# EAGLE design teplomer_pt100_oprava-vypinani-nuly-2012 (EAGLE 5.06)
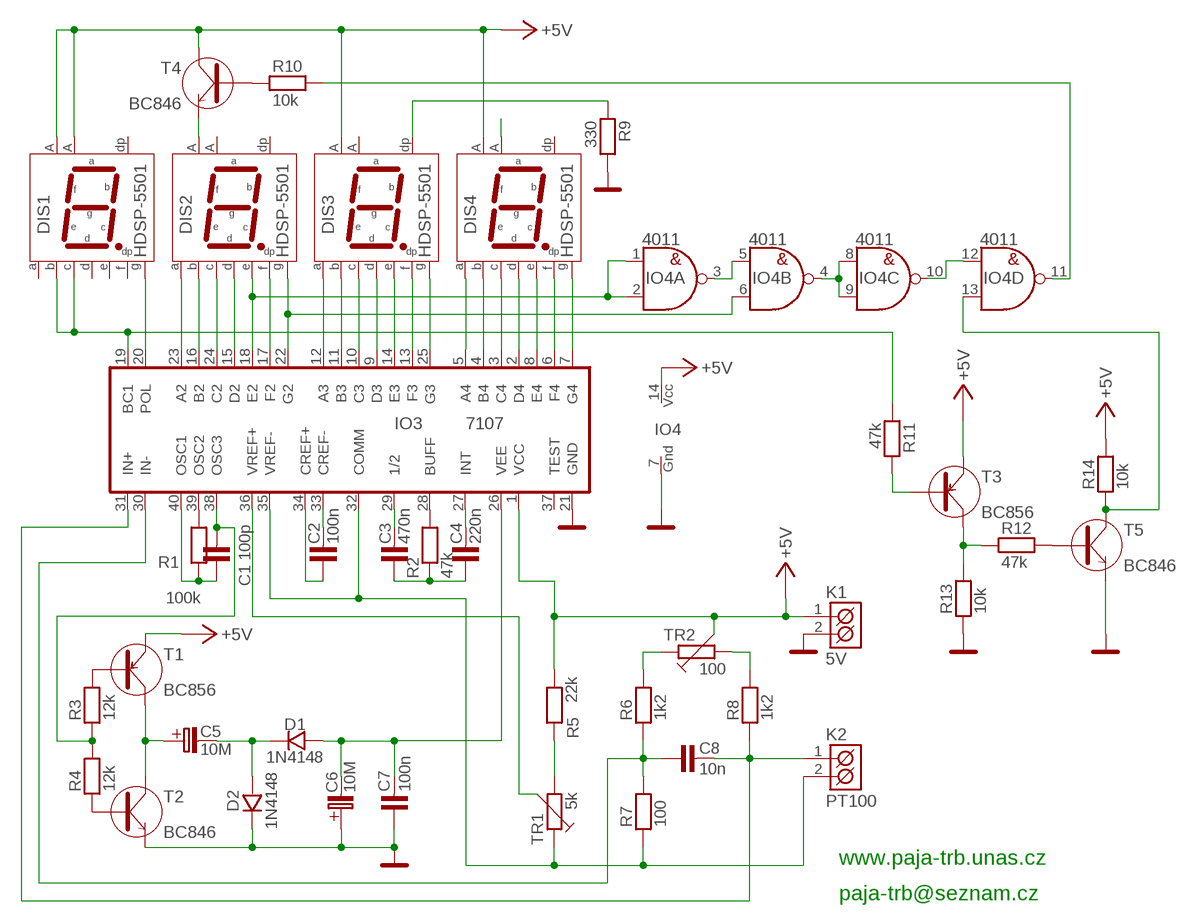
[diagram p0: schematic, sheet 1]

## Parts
C1  100p  C-KERAMIK_SMD_1206  [1206]
C2  100n  100N-J/63V  [RM5_2,5]
C3  470n  470N-J/63V  [RM5_3,2]
C4  220n  220N-J/63V  [RM5_3,2]
C5  10M  10M/25V  [C_EL_2]
C6  10M  10M/25V  [C_EL_2]
C7  100n  C-KERAMIK_SMD_1206  [1206]
C8  10n  C-KERAMIK_SMD_1206  [1206]
D1  1N4148  1N4148_SMD_SOD80  [SOD-80]
D2  1N4148  1N4148_SMD_SOD80  [SOD-80]
DIS1  HDSP-5501  [HDSP-M]
DIS2  HDSP-5501  [HDSP-M]
DIS3  HDSP-5501  [HDSP-M]
DIS4  HDSP-5501  [HDSP-M]
IO3  7107  [DIL40]
IO4  4011  [DIL14]
K1  5V  ARK500/2  [ARK500/2]
K2  PT100  ARK500/2  [ARK500/2]
R1  100k  R_SMD_1206  [1206]
R2  47k  R_SMD_1206  [1206]
R3  12k  R_SMD_1206  [1206]
R4  12k  R_SMD_1206  [1206]
R5  22k  R_SMD_1206  [1206]
R6  1k2  R_SMD_1206  [1206]
R7  100  R_SMD_1206  [1206]
R8  1k2  R_SMD_1206  [1206]
R9  330  R_SMD_1206  [1206]
R10  10k  R_SMD_1206  [1206]
R11  47k  R_SMD_0805  [0805]
R12  47k  R_SMD_0805  [0805]
R13  10k  R_SMD_0805  [0805]
R14  10k  R_SMD_0805  [0805]
T1  BC856  [SOT-23]
T2  BC846  [SOT-23]
T3  BC856  [SOT-23]
T4  BC846  [SOT-23]
T5  BC846  [SOT-23]
TR1  5k  TRIMR64P  [64P]
TR2  100  TRIMR64P  [64P]

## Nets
+5V: DIS1.3(CA1) DIS1.8(CA2) DIS3.3(CA1) DIS4.3(CA1) IO3.1(VCC) IO4.14(N:VCC) K1.1(K1) R5.2 R14.2 T1.1(E) T3.2(E) T4.3(C) TR2.2
GND: C6.C+(C_EL+) C7.1 D2.K IO3.21(GND) IO4.7(N:GND) K1.2(K2) R9.2 R13.1 T2.1(E) T5.2(E)
N$1: IO3.39(OSC2) R1.2
N$2: C2.2 IO3.33(CREF-)
N$3: C1.2 IO3.38(OSC3) R3.1 R4.2
N$4: IO3.28(BUFF) R2.2
N$5: R3.2 T1.2(B)
N$6: R4.1 T2.2(B)
N$7: DIS4.8(CA2)
N$8: C5.C+(C_EL+) T1.3(C) T2.3(C)
N$9: R11.2 T3.1(B)
N$10: DIS2.4(C) IO3.24(C2)
N$11: R12.2 T5.1(B)
N$12: C5.C-(C_EL-) D1.K D2.A
N$13: DIS2.6(B) IO3.16(B2)
N$15: R12.1 R13.2 T3.3(C)
N$16: R5.1 TR1.3
N$17: IO3.32(COMM) IO3.35(VREF-) K2.2(K2) R7.1 TR1.1
N$18: C8.1 IO3.30(IN-) R6.1 R7.2
N$19: R6.2 TR2.1
N$20: R8.2 TR2.3
N$21: C8.2 IO3.31(IN+) K2.1(K1) R8.1
N$22: IO4.13(D:IN2) R14.1 T5.3(C)
N$23: C1.1 IO3.40(OSC1) R1.1
N$24: C2.1 IO3.34(CREF+)
N$25: C3.2 IO3.29(1/2)
N$26: C4.2 IO3.27(INT)
N$27: C3.1 C4.1 R2.1
N$29: IO3.36(VREF+) TR1.2
N$49: DIS2.7(A) IO3.23(A2)
N$50: DIS2.2(D) IO3.15(D2)
N$53: R10.1 T4.2(B)
N$54: DIS2.10(G) IO3.22(G2) IO4.6(B:IN2)
N$55: DIS2.9(F) IO3.17(F2)
N$56: DIS3.4(C) IO3.10(C3)
N$57: DIS3.6(B) IO3.11(B3)
N$58: DIS3.7(A) IO3.12(A3)
N$59: DIS3.2(D) IO3.9(D3)
N$60: DIS3.1(E) IO3.14(E3)
N$61: DIS3.10(G) IO3.25(G3)
N$62: DIS3.9(F) IO3.13(F3)
N$63: DIS4.4(C) IO3.3(C4)
N$64: DIS4.6(B) IO3.4(B4)
N$65: DIS4.7(A) IO3.5(A4)
N$66: DIS4.2(D) IO3.2(D4)
N$67: DIS4.1(E) IO3.8(E4)
N$68: DIS4.10(G) IO3.7(G4)
N$69: DIS4.9(F) IO3.6(F4)
N$71: DIS1.4(C) DIS1.6(B) IO3.19(BC1) R11.1
N$72: DIS1.10(G) IO3.20(POL)
N$73: IO4.11(D:OUT1) R10.2
N$74: DIS2.1(E) IO3.18(E2) IO4.1(A:IN1) IO4.2(A:IN2)
N$75: IO4.3(A:OUT1) IO4.5(B:IN1)
N$76: IO4.4(B:OUT1) IO4.8(C:IN1) IO4.9(C:IN2)
N$77: IO4.10(C:OUT1) IO4.12(D:IN1)
N$78: DIS2.3(CA1) T4.1(E)
N$79: DIS3.5(DP) R9.1
VEE: C6.C-(C_EL-) C7.2 D1.A IO3.26(VEE)
Unconnected: DIS1.1(E) DIS1.2(D) DIS1.5(DP) DIS1.7(A) DIS1.9(F) DIS2.5(DP) DIS2.8(CA2) DIS3.8(CA2) DIS4.5(DP) IO3.37(TEST)

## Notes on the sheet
- 0°C
- 100°C
- www.paja-trb.unas.cz
- paja-trb@seznam.cz

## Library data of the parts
C1 C7 C8 = #PaJa_22:C-KERAMIK: Kondenzator - keramicky
C2 = #PaJa_C-folie:100N-J/63V
C3 = #PaJa_C-folie:470N-J/63V
C4 = #PaJa_C-folie:220N-J/63V
C5 C6 = #PaJa_C-el_2:10M/25V
D1 D2 = #PaJa_22:1N4148: Univerzalni dioda - 0,15A, 75V
DIS1-DIS4 = #PaJa_22:HDSP-5501: LED displej - SA - 14,2 mm - cervena
IO3 = #PaJa_22:7107: IO - A/D prevodnik + budic 7seg. displeje (3 a 1/2 mistny)
IO4 = #PaJa_22:4011: IO - 2vstup. NAND - 4x
K1 K2 = #PaJa_22:ARK500/2: Svorkovnice - roztec 5mm - dvojita
R1-R10 = #PaJa_22:R: Rezistor
R11-R14 = #PaJa_31:R: Rezistor
T1 = #PaJa_22:BC856: SMD tranzistor - PNP - ekv. BC556
T2 T4 = #PaJa_22:BC846: SMD tranzistor - NPN - ekv. BC546
T3 = #PaJa_31:BC856: SMD tranzistor - PNP - ekv. BC556
T5 = #PaJa_31:BC846: SMD tranzistor - NPN - ekv. BC546
TR1 TR2 = #PaJa_22:TRIMR: Trimr

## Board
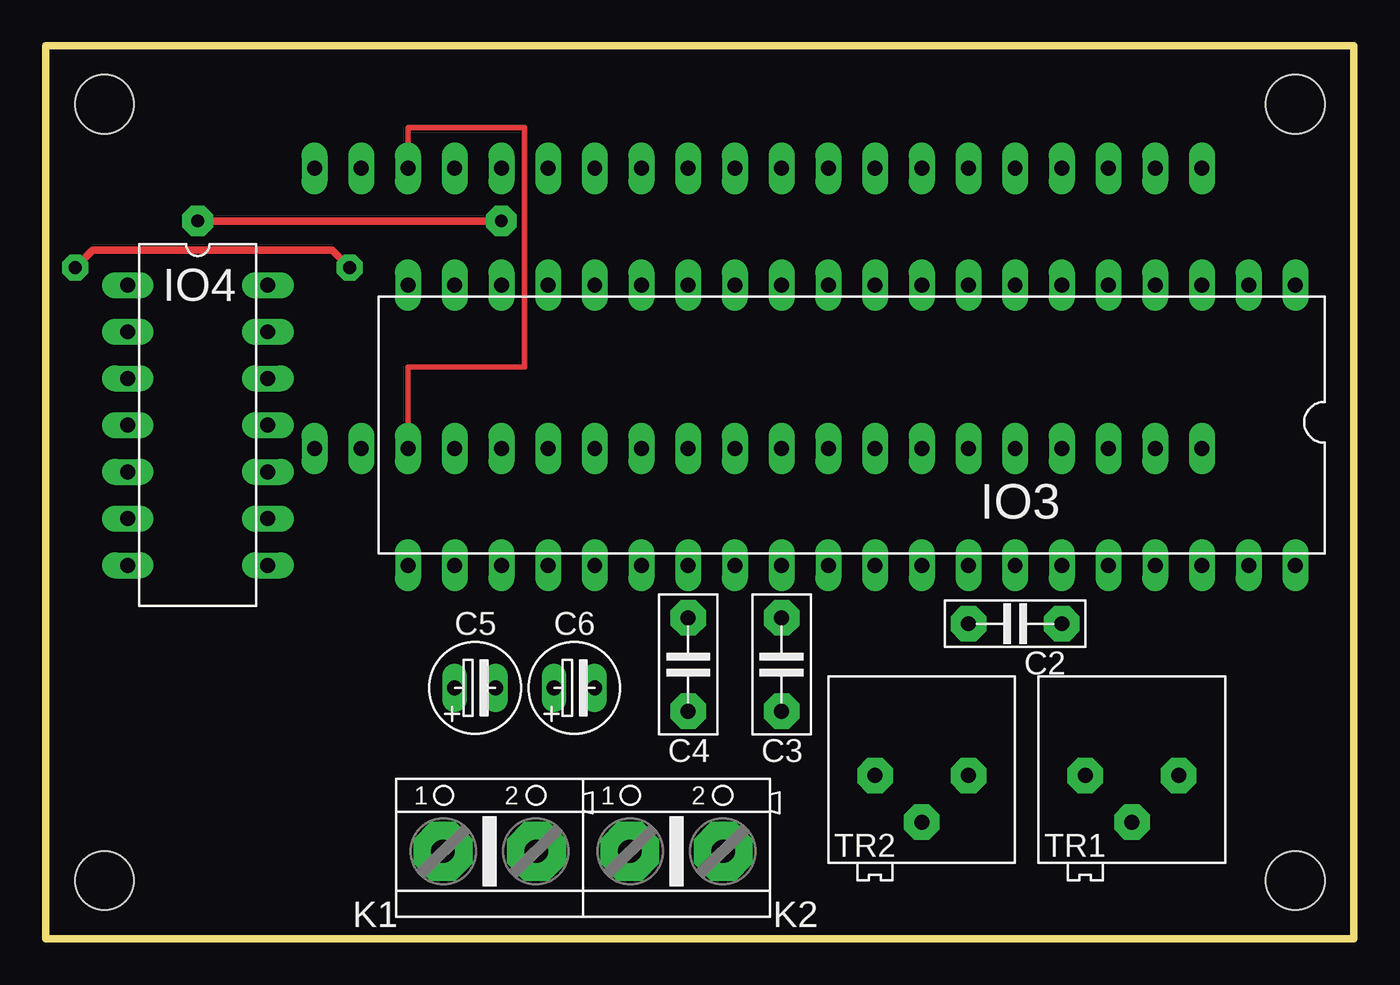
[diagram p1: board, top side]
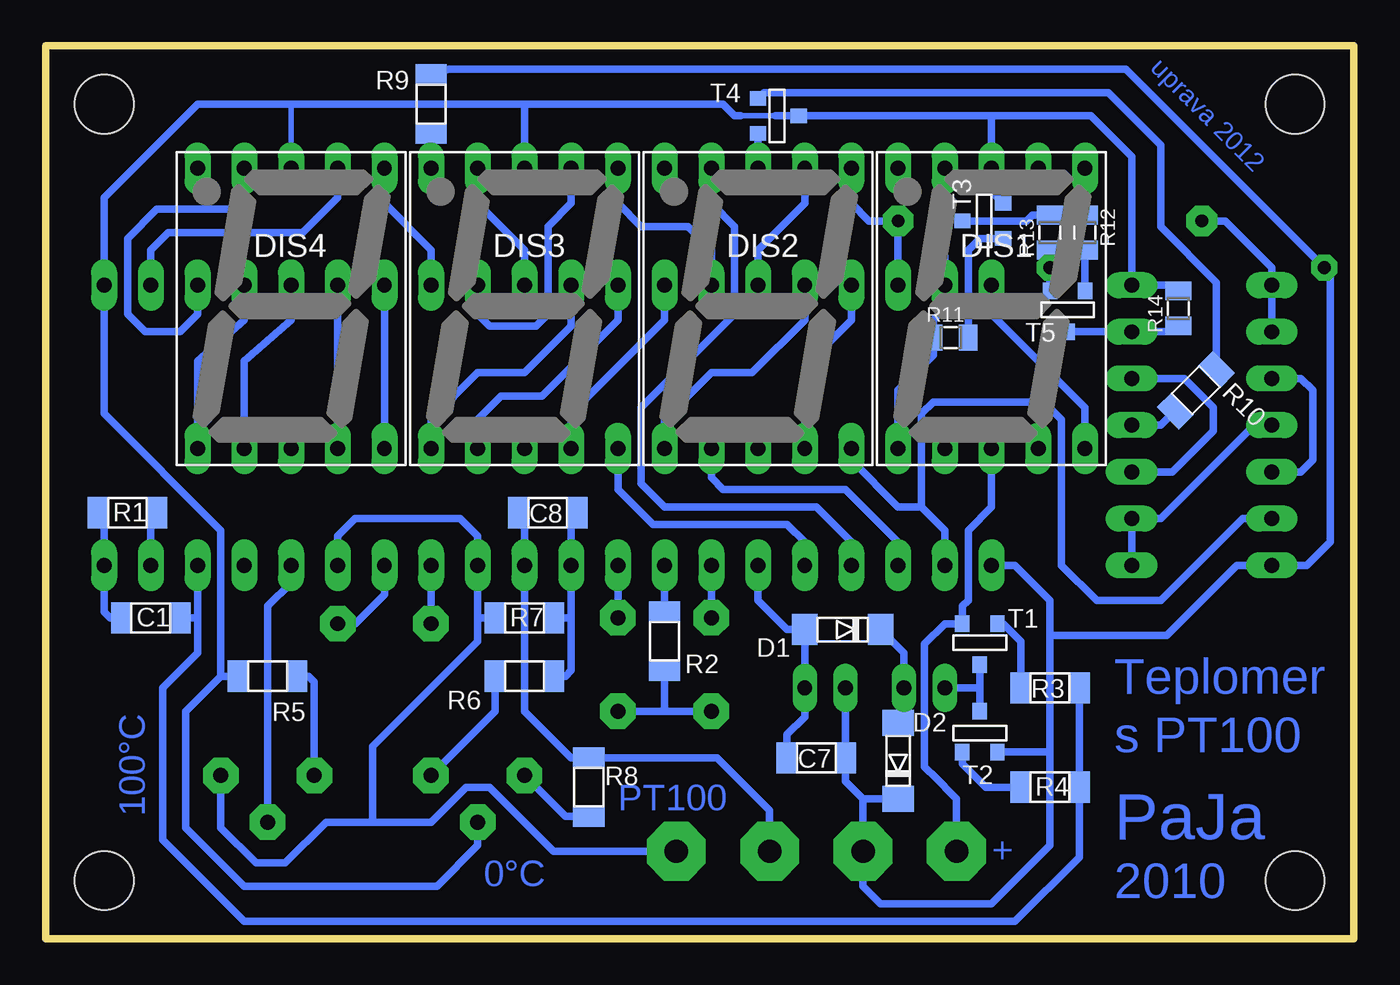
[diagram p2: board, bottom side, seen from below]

Size 71.11 x 48.57 mm. Coordinates in mm from the lower left corner, seen from the top.
Outline: 0,0 71.11,0 71.11,48.57 0,48.57 0,0
Copper layers (1*16): Top 0.035mm / dielectric 1.5mm / Bottom 0.035mm
Design rules "default": minimum track width 10mil, minimum drill 24mil, track to track 8mil, track to pad 8mil, pad to pad 8mil, via to via 8mil, smd to smd 8mil, copper to edge 40mil, drill to drill 8mil, minimum pad ring 10mil, minimum via ring 8mil, stop-mask expansion 4mil, vias tented up to drill 0mil, thermal gap 10mil
Holes 3.2 mm at 3.17,3.17 3.17,45.4 67.94,45.4 67.94,3.17

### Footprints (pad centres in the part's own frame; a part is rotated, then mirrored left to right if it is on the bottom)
1206 = smd 1.143 x 1.702: 1 -1.587,0; 2 1.587,0
RM5_2,5 = drill 0.813 pad 1.93 octagon: 1 -2.54,0; 2 2.54,0
RM5_3,2 = drill 0.813 pad 1.93 octagon: 1 -2.54,0; 2 2.54,0
C_EL_2 = drill 0.813 pad 1.27 long: C+ 0,0; C- 2.223,0
SOD-80 = smd 1.397 x 1.702: A 1.905,0; K -2.223,0
HDSP-M = drill 0.813 pad 1.4 long: 1 -5.08,-7.62; 2 -2.54,-7.62; 3 0,-7.62; 4 2.54,-7.62; 5 5.08,-7.62; 6 5.08,7.62; 7 2.54,7.62; 8 0,7.62; 9 -2.54,7.62; 10 -5.08,7.62
DIL40 = drill 0.813 pad 1.4 long: 1 -22.86,-7.62; 2 -20.32,-7.62; 3 -17.78,-7.62; 4 -15.24,-7.62; 5 -12.7,-7.62; 6 -10.16,-7.62; 7 -7.62,-7.62; 8 -5.08,-7.62; 9 -2.54,-7.62; 10 0,-7.62; 11 2.54,-7.62; 12 5.08,-7.62; 13 7.62,-7.62; 14 10.16,-7.62; 15 12.7,-7.62; 16 15.24,-7.62; 17 17.78,-7.62; 18 20.32,-7.62; 19 22.86,-7.62; 20 25.4,-7.62; 21 25.4,7.62; 22 22.86,7.62; 23 20.32,7.62; 24 17.78,7.62; 25 15.24,7.62; 26 12.7,7.62; 27 10.16,7.62; 28 7.62,7.62; 29 5.08,7.62; 30 2.54,7.62; 31 0,7.62; 32 -2.54,7.62; 33 -5.08,7.62; 34 -7.62,7.62; 35 -10.16,7.62; 36 -12.7,7.62; 37 -15.24,7.62; 38 -17.78,7.62; 39 -20.32,7.62; 40 -22.86,7.62
DIL14 = drill 0.813 pad 1.4 long: 1 -7.62,-3.81; 2 -5.08,-3.81; 3 -2.54,-3.81; 4 0,-3.81; 5 2.54,-3.81; 6 5.08,-3.81; 7 7.62,-3.81; 8 7.62,3.81; 9 5.08,3.81; 10 2.54,3.81; 11 0,3.81; 12 -2.54,3.81; 13 -5.08,3.81; 14 -7.62,3.81
ARK500/2 = drill 1.27 pad 3.2 octagon: 1 -2.54,0; 2 2.54,0
0805 = smd 1.016 x 1.422: 1 -0.953,0; 2 0.953,0
SOT-23 = smd 0.787 x 0.889: 1 0.953,-0.953; 2 -0.953,-0.953; 3 0,1.27
SOT-23' = smd 0.787 x 0.889: 1 -0.953,-0.953; 2 0.953,-0.953; 3 0,1.27
64P = drill 0.813 pad 1.93 octagon: 1 0,2.54; 2 2.54,0; 3 0,-2.54

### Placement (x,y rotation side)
C1  65.41,17.46 0 bottom
C2  52.7,17.14 180 top
C3  40.01,14.92 90 top
C4  34.92,14.92 90 top
C5  22.23,13.65 0 top
C6  27.62,13.65 0 top
C7  29.21,9.84 180 bottom
C8  43.81,23.18 180 bottom
D1  27.94,16.83 180 bottom
D2  24.77,9.84 90 bottom
DIS1  19.68,34.29 180 bottom
DIS2  32.38,34.29 180 bottom
DIS3  45.09,34.29 180 bottom
DIS4  57.78,34.29 180 bottom
IO3  45.09,27.94 180 top
IO4  8.26,27.94 270 top
K1  24.13,4.76 0 top
K2  34.29,4.76 0 top
R1  66.67,23.18 0 bottom
R2  37.47,16.19 90 bottom
R3  16.51,13.65 180 bottom
R4  16.51,8.26 0 bottom
R5  59.05,14.29 180 bottom
R6  45.09,14.29 180 bottom
R7  45.09,17.46 0 bottom
R8  41.59,8.26 270 bottom
R9  50.16,45.4 90 bottom
R10  8.57,29.84 225 bottom
R11  21.91,32.7 0 bottom
R12  14.61,38.42 270 bottom
R13  16.51,38.42 90 bottom
R14  9.53,34.29 90 bottom
T1  20.32,16.19 180 bottom
T2  20.32,11.11 0 bottom
T3  BC856  [SOT-23']  20,39.05 90 bottom
T4  31.43,44.77 270 bottom
T5  BC846  [SOT-23']  15.56,34.29 180 bottom
TR1  59.05,8.89 270 top
TR2  47.62,8.89 270 top

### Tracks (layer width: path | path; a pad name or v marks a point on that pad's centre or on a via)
+5V
  Top 0.305: DIS1.8 19.68,31.11 26.04,31.11 26.04,44.13 19.68,44.13 DIS1.3
  Bottom 0.305: 31.43,44.77 33.34,44.77 | 57.78,45.4 DIS4.3
  Bottom 0.406: 45.09,45.4 57.78,45.4 62.87,45.4 67.94,40.32 IO3.1 67.94,28.57 61.59,22.23 61.59,14.29 | 22.86,8.89 23.18,9.21 23.34,9.37 23.34,16.03 22.23,17.14 T1.1 21.27,18.1 20.95,18.41 20.95,22.23 19.68,23.5 DIS1.8 | 22.86,8.89 | 22.86,8.89 21.59,7.62 K1.1 | DIS1.3 19.68,43.81 | 31.43,44.77 T4.3 19.68,44.77 | 33.34,44.77 33.66,44.77 34.29,45.4 45.09,45.4 | 45.09,45.4 DIS3.3 | TR2.2 47.62,5.08 49.85,2.86 60.33,2.86 63.5,6.03 63.5,12.38 61.59,14.29 | 61.59,14.29 R5.2 | T3.2 19.68,40.64 DIS1.3 | DIS1.3 19.68,44.77 | 19.68,44.77 14.29,44.77 12.06,42.55 IO4.14 9.84,35.56 R14.2
GND  (via drill 0.7 pad 1.42)
  Top 0.406: v16.51,36.51 15.56,37.47 2.54,37.47 v1.59,36.51
  Bottom 0.406: 16.51,10.16 T2.1 | C6.C+ C7.1 27.62,8.57 26.67,7.62 | R9.2 49.21,47.31 12.38,47.31 v1.59,36.51 1.27,36.2 1.27,21.59 2.54,20.32 IO4.7 6.35,20.32 10.16,16.51 16.51,16.51 | IO3.21 18.41,20.32 16.51,18.41 16.51,16.51 | 16.51,10.16 16.51,16.51 | 16.51,10.16 16.51,5.08 19.68,1.91 25.72,1.91 26.67,2.86 K1.2 26.67,7.62 | 26.67,7.62 D2.K | R13.1 v16.51,36.51 T5.2
N$1
  Bottom 0.406: R1.2 65.41,22.86 IO3.39
N$2
  Bottom 0.406: C2.2 IO3.33
N$3
  Bottom 0.406: 62.87,17.46 IO3.38 | R3.1 R4.2 14.92,4.45 18.41,0.95 60.33,0.95 64.77,5.4 64.77,13.65 62.87,15.56 62.87,17.46 | 62.87,17.46 C1.2
N$4
  Bottom 0.406: R2.2 IO3.28
N$5
  Bottom 0.406: R3.2 18.1,16.19 19.05,17.14 T1.2
N$6
  Bottom 0.406: R4.1 20,8.26 21.27,9.53 T2.2
N$8
  Bottom 0.406: 20.32,13.65 C5.C+ | T2.3 20.32,13.65 | 20.32,13.65 T1.3
N$9
  Bottom 0.406: T3.1 20.32,38.1 20.95,37.47 R11.2
N$10
  Bottom 0.406: IO3.24 27.3,21.59 29.21,23.5 37.47,23.5 38.73,24.77 38.73,28.89 33.66,33.97 33.66,38.73 34.92,40.01 DIS2.4
N$11
  Bottom 0.406: T5.1 R12.2
N$12
  Bottom 0.406: D1.K 24.45,15.56 C5.C- 24.45,11.75 D2.A
N$13
  Bottom 0.406: IO3.16 29.84,33.66 32.7,30.8 34.92,30.8 37.47,28.26 DIS2.6
N$15
  Bottom 0.406: R12.1 R13.2 17.46,39.37 17.78,39.05 T3.3
N$16
  Bottom 0.406: R5.1 56.83,14.29 56.52,13.97 TR1.3
N$17
  Bottom 0.406: IO3.35 55.24,21.91 54.29,22.86 48.58,22.86 47.62,21.91 IO3.32 47.62,17.46 | 47.62,17.46 R7.1 | 47.62,17.46 47.62,16.19 53.34,10.48 53.34,6.35 | K2.2 43.5,4.76 46.99,8.26 48.26,8.26 50.16,6.35 53.34,6.35 | TR1.1 61.59,6.03 59.69,4.13 58.1,4.13 55.88,6.35 53.34,6.35
N$18
  Bottom 0.406: 42.55,17.46 R7.2 | 42.55,17.46 IO3.30 42.55,23.18 C8.1 | R6.1 42.86,14.29 42.55,14.61 42.55,17.46
N$19
  Bottom 0.406: R6.2 46.67,12.38 TR2.1
N$20
  Bottom 0.406: R8.2 42.86,6.67 TR2.3
N$21
  Bottom 0.406: C8.2 45.09,23.18 IO3.31 45.09,12.38 42.55,9.84 R8.1 34.61,9.84 31.75,6.99 K2.1
N$22
  Bottom 0.406: R14.1 9.84,33.02 IO4.13 T5.3
N$23
  Bottom 0.406: R1.1 67.94,23.18 IO3.40 67.94,17.78 67.63,17.46 C1.1
N$24
  Bottom 0.406: C2.1 54.29,17.14 52.7,18.73 IO3.34
N$25
  Bottom 0.406: C3.2 IO3.29
N$26
  Bottom 0.406: C4.2 IO3.27
N$27
  Bottom 0.406: 37.47,12.38 R2.1 | C4.1 37.47,12.38 | 37.47,12.38 C3.1
N$29
  Bottom 0.406: TR1.2 59.05,18.1 57.78,19.37 IO3.36
N$49
  Bottom 0.406: IO3.23 24.77,21.59 27.62,24.45 34.29,24.45 34.92,25.08 DIS2.7
N$50
  Bottom 0.406: IO3.15 32.38,37.47 29.84,40.01 DIS2.2
N$53
  Bottom 0.406: T4.2 32.07,46.04 13.34,46.04 10.48,43.18 10.48,38.73 7.45,35.71 R10.1
N$54
  Bottom 0.406: DIS2.10 27.3,26.04 24.77,23.5 23.5,23.5 | IO4.6 6.03,22.86 10.48,18.41 13.97,18.41 15.88,20.32 15.88,28.26 16.83,29.21 22.86,29.21 23.5,28.57 23.5,23.5 | 23.5,23.5 22.23,22.23 IO3.22
N$55
  Bottom 0.406: IO3.17 27.3,33.66 29.84,31.11 DIS2.9
N$56
  Bottom 0.406: IO3.10 45.09,37.47 47.62,40.01 DIS3.4
N$57
  Bottom 0.406: IO3.11 42.55,33.34 45.09,30.8 47.62,30.8 50.16,28.26 DIS3.6
N$58
  Bottom 0.406: IO3.12 40.01,33.66 44.13,29.53 46.35,29.53 47.62,28.26 DIS3.7
N$59
  Bottom 0.406: DIS3.2 42.55,40.01 43.81,38.73 43.81,33.97 44.45,33.34 46.99,33.34 47.62,33.97 IO3.9
N$60
  Bottom 0.406: IO3.14 34.92,37.47 36.2,38.73 38.73,38.73 40.01,40.01 DIS3.1
N$61
  Bottom 0.406: IO3.25 29.84,21.59 30.8,22.54 38.1,22.54 40.01,24.45 DIS3.10
N$62
  Bottom 0.406: IO3.13 37.47,33.66 42.55,28.57 DIS3.9
N$63
  Bottom 0.406: IO3.3 62.87,33.97 63.82,33.02 65.72,33.02 66.67,33.97 66.67,38.1 65.09,39.69 60.96,39.69 60.33,40.32 DIS4.4
N$64
  Bottom 0.406: DIS4.6 62.87,31.43 60.33,33.66 IO3.4
N$65
  Bottom 0.406: DIS4.7 60.33,31.43 57.78,33.66 IO3.5
N$66
  Bottom 0.406: DIS4.2 55.24,40.32 57.15,38.42 64.45,38.42 65.41,37.47 IO3.2
N$67
  Bottom 0.406: DIS4.1 52.7,40.01 50.16,37.47 IO3.8
N$68
  Bottom 0.406: DIS4.10 IO3.7
N$69
  Bottom 0.406: DIS4.9 IO3.6
N$71
  Bottom 0.406: DIS1.4 22.23,40.64 22.86,40.01 22.86,37.78 22.23,37.15 IO3.19 22.23,34.29 22.86,33.66 R11.1 22.86,31.75 24.77,29.84 DIS1.6
N$72
  Bottom 0.406: IO3.20 19.68,33.97 14.61,28.89 DIS1.10
N$73
  Bottom 0.406: IO4.11 10.48,27.94 R10.2 9.53,28.89
N$74  (via drill 0.7 pad 1.68)
  Top 0.406: v8.26,39.05 v24.77,39.05
  Bottom 0.406: 24.77,37.47 IO3.18 v24.77,39.05 26.35,39.05 27.3,40.01 DIS2.1 | IO4.2 IO4.1 4.45,36.51 6.99,39.05 v8.26,39.05
N$75
  Bottom 0.406: IO4.3 2.86,30.48 2.22,29.84 2.22,26.04 2.86,25.4 IO4.5
N$76
  Bottom 0.406: IO4.8 IO4.9 10.48,22.86 5.4,27.94 IO4.4
N$77
  Bottom 0.406: IO4.10 9.84,25.4 7.62,27.62 7.62,28.89 9.21,30.48 IO4.12
N$78
  Bottom 0.406: DIS2.3 T4.1
N$79
  Bottom 0.406: DIS3.5 R9.1
VEE
  Bottom 0.406: C7.2 30.8,11.11 29.84,12.06 C6.C- D1.A 30.8,16.83 32.38,18.41 IO3.26

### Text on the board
Bottom: uprava 2012 | Teplomer | s PT100 | PT100 | 100°C | PaJa | + | 0°C | 2010
tValues: Gnd
Zapojeni: 0°C | 100°C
